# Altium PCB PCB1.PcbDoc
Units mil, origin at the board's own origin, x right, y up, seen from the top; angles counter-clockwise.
Board outline 6299.21 x 3937.01 mil, 4 copper layers (Top Layer, Top inner, Bottom inner, Bottom Layer), stack 60.556 mil thick; 113 components, 82 nets, 381 pads, 76 vias.
Unrouted connection lines stored in the file: 50.
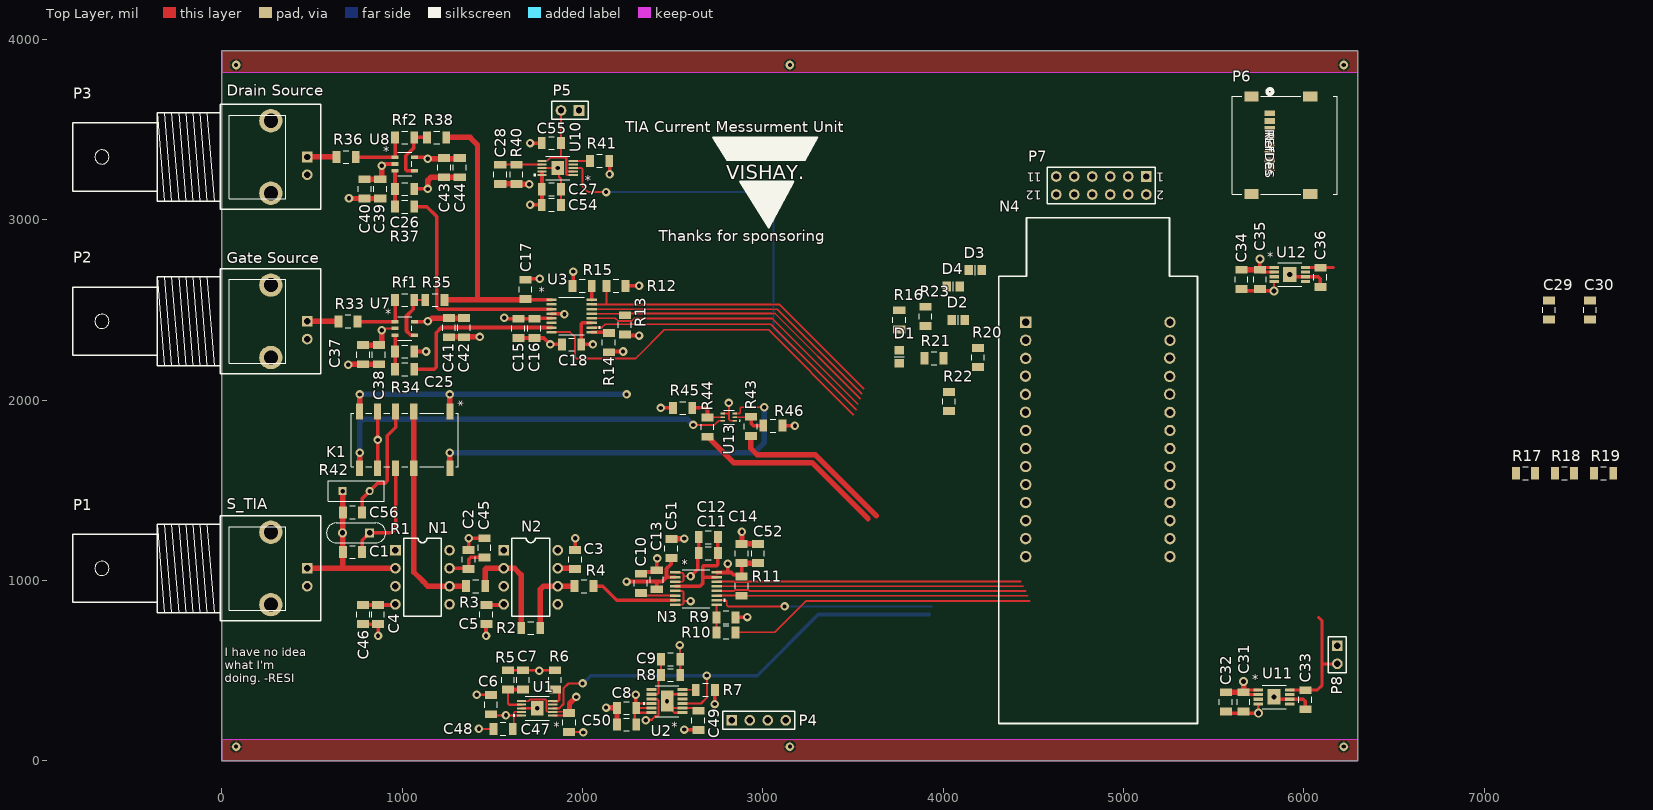
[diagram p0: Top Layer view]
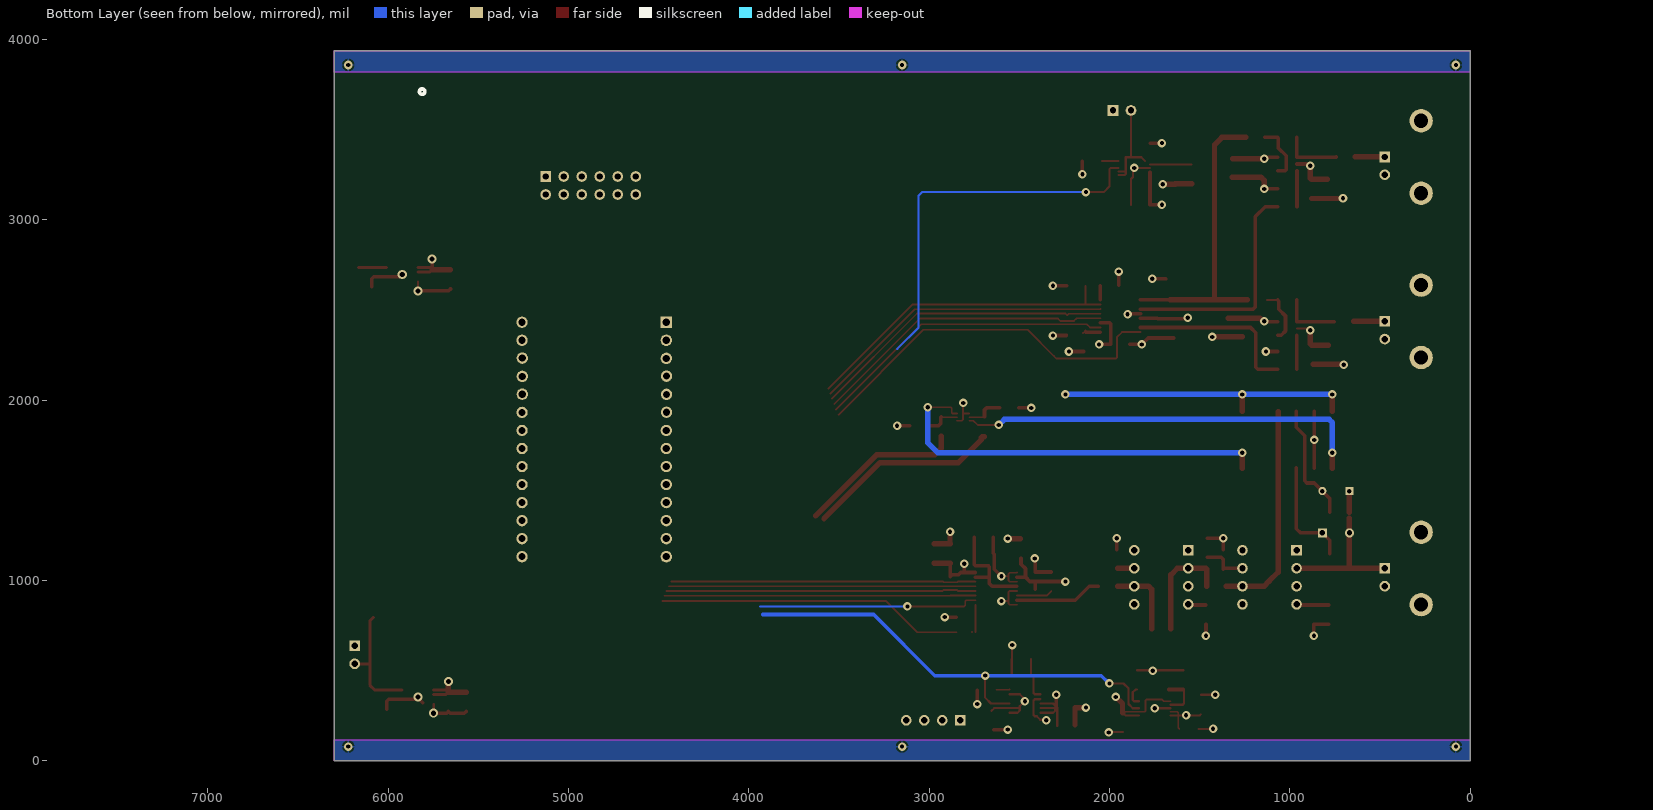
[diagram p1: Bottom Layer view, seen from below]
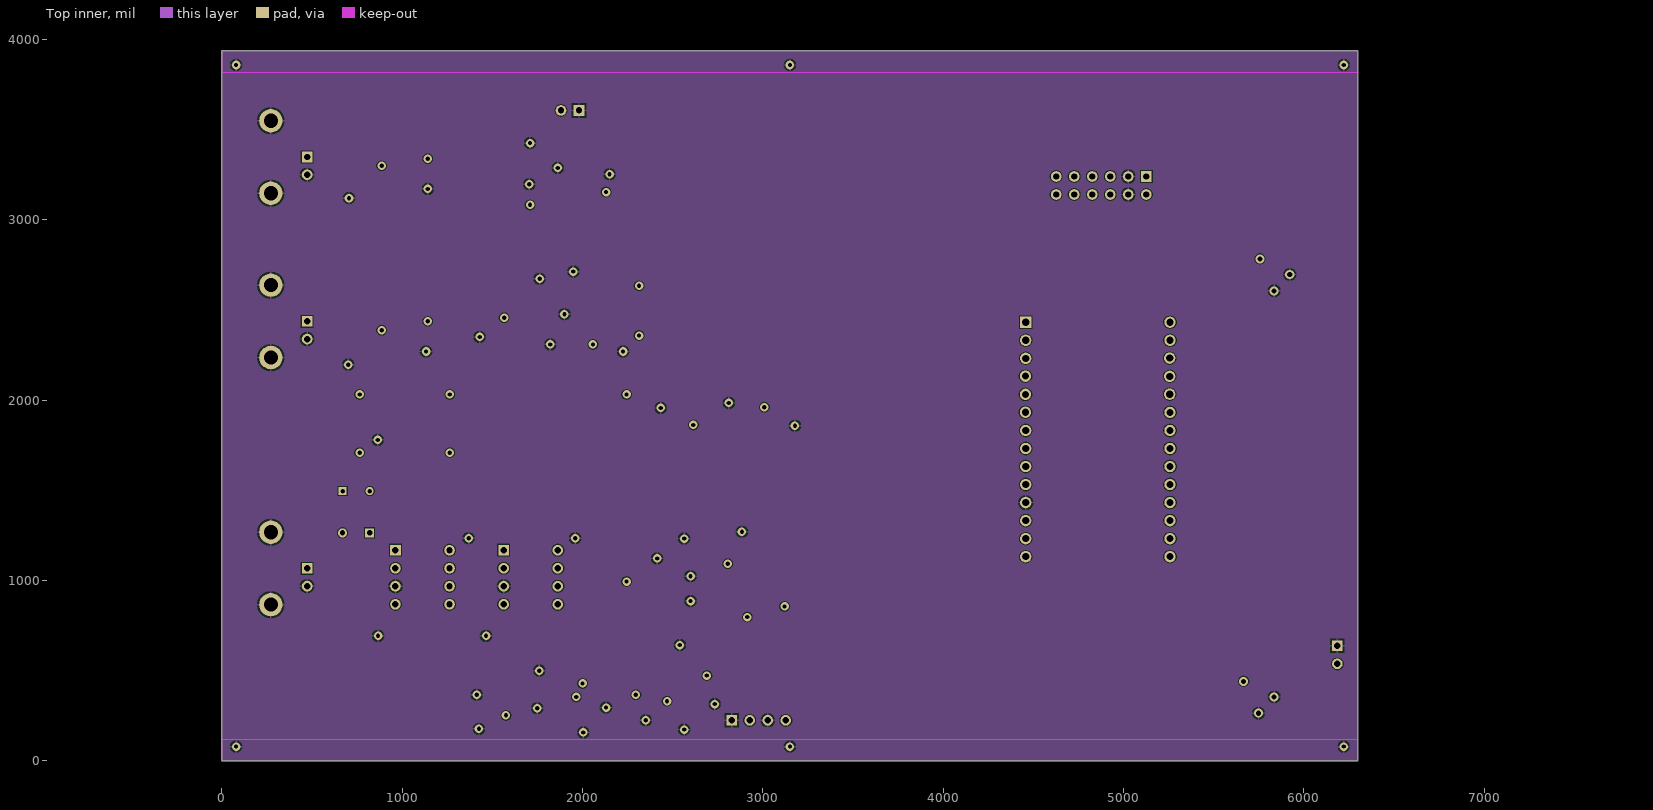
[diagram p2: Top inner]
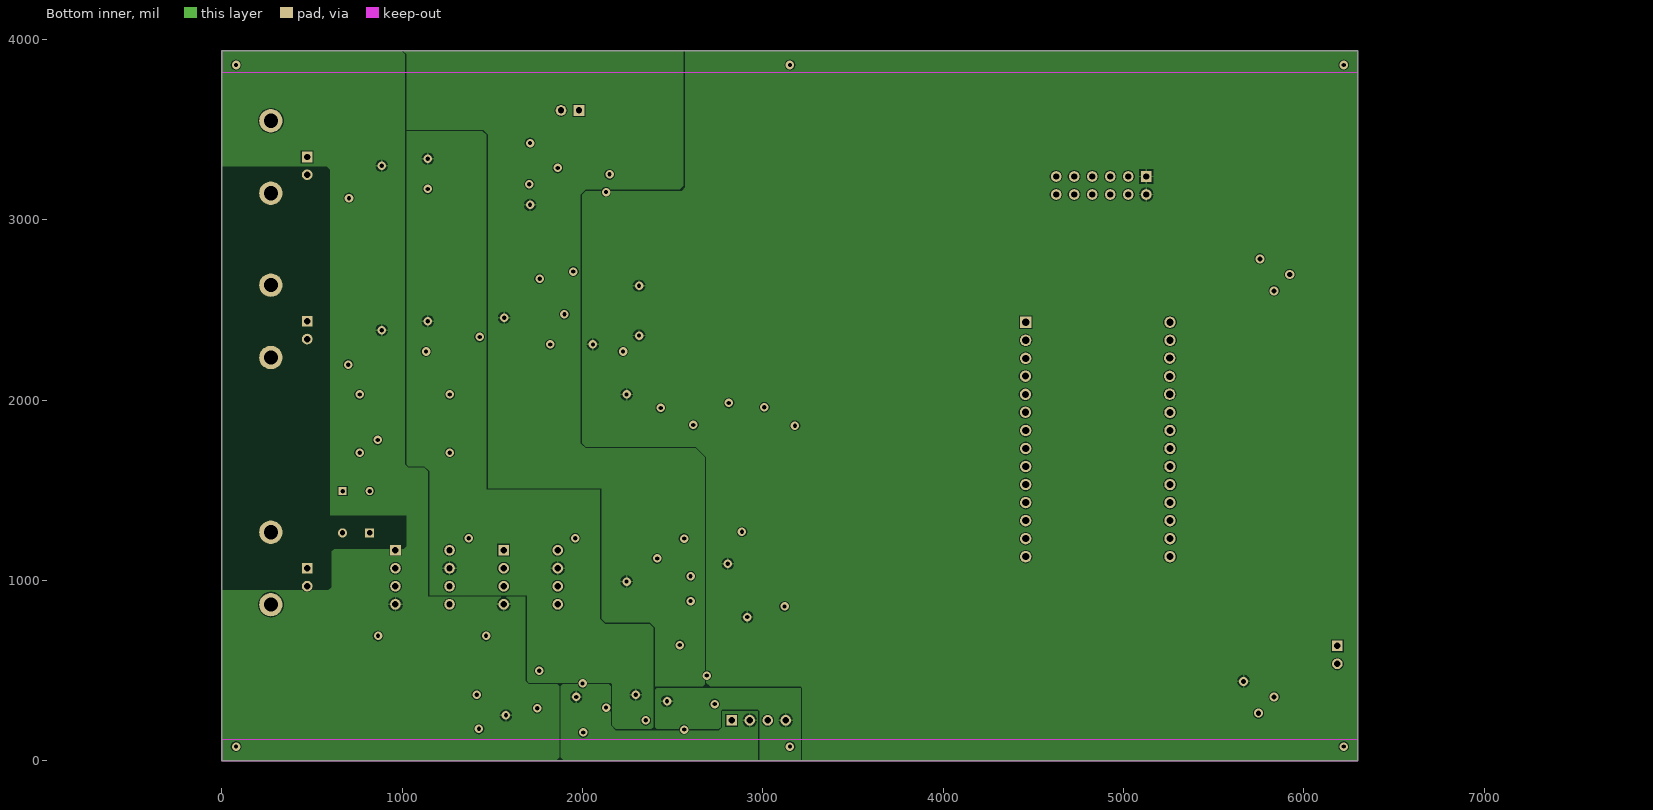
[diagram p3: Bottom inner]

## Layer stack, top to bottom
Top Solder: solder mask 0.4, Solder Resist, Dk 3.5
Top Layer: signal copper 1.4
Dielectric 4: prepreg 6, PP-006, Dk 4.4
Top inner: signal copper 1.378
Dielectric 1: dielectric 43, FR-4, Dk 4.8
Bottom inner: signal copper 1.378
Dielectric 5: prepreg 6, PP-006, Dk 4.4
Bottom Layer: signal copper 1.4
Bottom Solder: solder mask 0.4, Solder Resist, Dk 3.5

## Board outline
0,0 6299.21,0 6299.21,3937.01 0,3937.01

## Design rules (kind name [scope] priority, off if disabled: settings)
Clearance [All] p1: gap=5 ignorepadtopadclearanceinfootprint=TRUE except(1: THPad-THPad)
MinimumSolderMaskSliver THT_21-0248A_Q3-1_MXM [HasFootprint('21-0248A_Q3-1_MXM')] p1: minsoldermaskwidth=0
MinimumSolderMaskSliver [All] p2: minsoldermaskwidth=5
PolygonConnect [All] p1: connectstyle=Relief reliefconductorwidth=10 reliefentries=4 polygonreliefangle="90 Angle" airgapwidth=10
RoutingVias [All] p1: holewidth=23.62 width=47.24 viastyle="Through Hole" minholewidth=11.81 minwidth=23.62 maxholewidth=39.37 maxwidth=78.74
SilkToSolderMaskClearance SilkToSolderMaskClearance_1 [HasFootprint('BNC_RA CON')] p1: minsilkscreentomaskgap=0 clearancetoexposedcopper=TRUE
SilkToSolderMaskClearance [IsPad] p2: minsilkscreentomaskgap=5 clearancetoexposedcopper=TRUE
SolderMaskExpansion [All] p1: expansion=4 istentingtop=FALSE
Width Source [InNet('M_source')] p1: maxlimit=100 minlimit=10 preferedwidth=30
Width Width_1 [All] p2: maxlimit=30 minlimit=10 preferedwidth=30
28 further rules are at their usual default settings.

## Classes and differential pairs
component class U_Digital_Psu: C31 C32 C33 C34 C35 C36 U11 U12
component class U_Analog_PSU_5: C27 C28 C54 R40 R41 U10
component class U_Source_TIA: C1 C2 C3 C4 C5 C45 C46 C56 K1 N1 N2 R1 R2 R3 R4 R42
component class U_OPV_psu: C6 C7 C8 C9 C47 C48 C49 C50 R5 R6 R7 R8 U1 U2
component class U_DAC_Buffer_Filter: C25 C26 C37 C38 C39 C40 C41 C42 C43 C44 R33 R34 R35 R36 R37 R38 Rf1 Rf2 U7 U8
component class U_CortexM3_dev: C29 C30 D1 D2 D3 D4 N4 P6 P7 R16 R17 R18 R19 R20 R21 R22 R23
component class U_ADC_8681: C10 C11 C12 C13 C14 C51 C52 N3 R9 R10 R11
component class U_AD_5689_DAC: C15 C16 C17 C18 R12 R13 R14 R15 U3
component class Top_Sheet: C55 P1 P2 P3 P4 P5 P8 R43 R44 R45 R46 U13

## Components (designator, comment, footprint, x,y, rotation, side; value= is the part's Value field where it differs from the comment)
C1 "22pF" C1206-KUE 724.41,1157.48 r0 top
C2 "100nF" C1206-KUE 1368.11,1116.14 r270 top
C3 "100nF" C1206-KUE 1958.66,1116.14 r270 top
C4 "100nF" C1206-KUE 866.14,811.02 r90 top
C5 "100nF" C1206-KUE 1466.54,811.02 r90 top
C6 "10uF" C1206-KUE 1492.39,311.02 r270 top
C7 "4.7uF" C1206-KUE 1669.55,448.82 r270 top
C8 "10uF" C1206-KUE 2244.09,293.35 r0 top
C9 "4.7uF" C1206-KUE 2488.19,562.99 r180 top
C10 "10uF" C1206-KUE 2322.83,984.25 r270 top
C11 "100nF" C1206-KUE 2696.85,1151.57 r0 top
C12 "10uF" C1206-KUE 2696.85,1240.16 r0 top
C13 "0.1uF" C1206-KUE 2411.42,1003.94 r270 top
C14 "0.1uF" C1206-KUE 2881.89,1149.61 r270 top
C15 "10uF" C1206-KUE 1643.7,2397.64 r90 top
C16 "0.1uF" C1206-KUE 1732.28,2397.64 r90 top
C17 "0.1uF" C1206-KUE 1683.07,2614.17 r270 top
C18 "0.1uF" C1206-KUE 1938.98,2309.06 r0 top
C25 "1uF" C1206-KUE 1013.78,2269.69 r180 top
C26 "1uF" C1206-KUE 1013.78,3171.26 r180 top
C27 "10uF" C1206-KUE 1826.77,3169.29 r180 top
C28 "4.7uF" C1206-KUE 1543.31,3251.97 r90 top
C29 "100nF" C1206-KUE 7358.27,2500 r90 top
C30 "1uF" C1206-KUE 7586.61,2500 r90 top
C31 "100nF" C1206-KUE 5665.35,326.77 r90 top
C32 "10uF" C1206-KUE 5566.93,326.77 r90 top
C33 "10uF" C1206-KUE 6007.87,338.58 r90 top
C34 "100nF" C1206-KUE 5653.54,2669.29 r90 top
C35 "10uF" C1206-KUE 5755.91,2669.29 r90 top
C36 "4.7uF" C1206-KUE 6090.55,2681.1 r90 top
C37 "100nF" C1206-KUE 783.46,2251.97 r90 top
C38 "1uF" C1206-KUE 870.08,2251.97 r90 top
C39 "100nF" C1206-KUE 877.95,3171.26 r90 top
C40 "1uF" C1206-KUE 791.34,3171.26 r90 top
C41 "100nF" C1206-KUE 1259.84,2401.57 r90 top
C42 "1uF" C1206-KUE 1342.52,2401.57 r90 top
C43 "100nF" C1206-KUE 1232.28,3289.37 r90 top
C44 "1uF" C1206-KUE 1318.9,3289.37 r90 top
C45 "10uF" C1206-KUE 1456.69,1181.1 r270 top
C46 "10uF" C1206-KUE 783.46,811.02 r270 top
C47 "10uF" C1206-KUE 1925.46,212.6 r90 top
C48 "100nF" C1206-KUE 1559.32,177.17 r0 top
C49 "10uF" C1206-KUE 2641.73,224.41 r90 top
C50 "100nF" C1206-KUE 2244.09,200.79 r0 top
C51 "10uF" C1206-KUE 2492.13,1177.17 r270 top
C52 "10uF" C1206-KUE 2972.44,1149.61 r270 top
C54 "100nF" C1206-KUE 1826.77,3082.68 r180 top
C55 "100nF" C1206-KUE 1826.77,3425.2 r0 top
C56 "22pF" C1206-KUE 724.41,1377.95 r0 top
D1 "GREEN" 6-0805_N-KUE 3755.92,2240.13 r90 top
D2 "GREEN" 6-0805_N-KUE 4082.68,2444.88 r0 top
D3 "RED" 6-0805_N-KUE 4177.17,2720.47 r0 top
D4 "RED" 6-0805_N-KUE 4055.12,2629.92 r0 top
K1 "G6SK-2F-TR DC3" "RELAY_G6SK-2F DC3_OMR" 763.78,1622.05 r270 top
N1 "LMC6001AIN/NOPB" DIP8 1112.2,1017.72 r270 top
N2 "LMC6001AIN/NOPB" DIP8 1712.6,1017.72 r270 top
N3 "ADS8681IPW" PW16_TEX 2627.95,954.72 r0 top
N4 "STM32F103" DIP28 4307.09,3011.81 r0 top
P1 "BNC" "BNC_RA CON" 472.44,1066.93 r0 top
P2 "BNC" "BNC_RA CON" 472.44,2437.01 r0 top
P3 "BNC" "BNC_RA CON" 472.44,3348.43 r0 top
P4 "Header 4" HDR1X4 2826.77,224.41 r0 top
P5 "Header 2" HDR1X2 1980.32,3606.3 r180 top
P6 "472192001" CONN_47219-2001_MOL 5893.7,3413.39 r270 top
P7 "Header 6X2" HDR2X6 5125.98,3240.16 r180 top
P8 "Header 2" HDR1X2 6185.04,637.8 r270 top
R1 "CNS020-10MP" RES_CNS020_VIS 818.9,1263.78 r180 top
R2 "10k" C1206-KUE 1712.6,736.22 r180 top
R3 "33k" C1206-KUE 1407.48,968.5 r180 top
R4 "10" C1206-KUE 2007.87,968.5 r180 top
R5 "78.7k" C1206-KUE 1586.61,448.82 r90 top
R6 "0" C1206-KUE 1846.72,448.82 r90 top
R7 "0" C1206-KUE 2681.1,393.7 r0 top
R8 "78.7k" C1206-KUE 2488.19,476.38 r0 top
R9 "10k" C1206-KUE 2795.28,795.28 r180 top
R10 "1k" C1206-KUE 2795.28,712.6 r180 top
R11 "4.7k" C1206-KUE 2881.89,968.5 r270 top
R12 "4.7k" C1206-KUE 2185.04,2633.86 r180 top
R13 "4.7k" C1206-KUE 2234.25,2417.32 r90 top
R14 "10k" C1206-KUE 2145.67,2318.9 r270 top
R15 "10k" C1206-KUE 1998.03,2633.86 r180 top
R16 "3.9k" C1206-KUE 3755.92,2444.86 r90 top
R17 "4.7k" C1206-KUE 7228.32,1594.48 r0 top
R18 "4.7k" C1206-KUE 7444.86,1594.48 r0 top
R19 "4.7k" C1206-KUE 7661.39,1594.48 r0 top
R20 "3.9k" C1206-KUE 4192.89,2236.21 r90 top
R21 "2.7k" C1206-KUE 3948.82,2232.28 r0 top
R22 "2.7k" C1206-KUE 4031.5,1992.13 r90 top
R23 "4.7k" C1206-KUE 3901.57,2464.57 r90 top
R33 "100" C1206-KUE 698.82,2437.01 r180 top
R34 "10k" C1206-KUE 1013.78,2171.26 r180 top
R35 "10k" C1206-KUE 1181.1,2555.12 r180 top
R36 "100" C1206-KUE 688.98,3348.43 r180 top
R37 "10k" C1206-KUE 1013.78,3072.83 r180 top
R38 "10k" C1206-KUE 1190.94,3456.69 r180 top
R40 "49.9k" C1206-KUE 1633.86,3251.97 r270 top
R41 "0" C1206-KUE 2094.49,3326.77 r0 top
R42 "Y0062100K000T9L" RES_S102K_7P62X2P67_VIS 669.29,1496.06 r0 top
R43 "1k" C1206-KUE 2933.07,1854.33 r270 top
R44 "1k" C1206-KUE 2692.91,1850.39 r270 top
R45 "10k" C1206-KUE 2555.12,1956.69 r180 top
R46 "10k" C1206-KUE 3055.12,1858.27 r0 top
Rf1 "20k" C1206-KUE 1013.78,2555.12 r180 top
Rf2 "20k" C1206-KUE 1013.78,3456.69 r180 top
U1 "LT3042EMSE#TRPBF" 05-08-1664_ADI 1748.29,291.34 r180 top
U2 "LT3094EMSE#TRPBF" MSE_05-08-1666_ADI 2468.5,330.71 r180 top
U3 "AD5689RBRUZ" RU_16_ADI 1938.98,2466.54 r0 top
U7 "OPA197IDBVR" DBV5_TEX 1013.78,2397.64 r0 top
U8 "OPA197IDBVR" DBV5_TEX 1013.78,3309.06 r0 top
U10 "LT3042EMSE#TRPBF" 05-08-1664_ADI 1862.2,3287.4 r180 top
U11 "TLV76733DGNR" VSSOP8_DGN_TEX 5834.65,354.33 r0 top
U12 "TLV76733DGNR" VSSOP8_DGN_TEX 5921.26,2696.85 r0 top
U13 "DMC2400UV-7" SON_400UV-7_DIO 2811.02,1905.51 r180 top

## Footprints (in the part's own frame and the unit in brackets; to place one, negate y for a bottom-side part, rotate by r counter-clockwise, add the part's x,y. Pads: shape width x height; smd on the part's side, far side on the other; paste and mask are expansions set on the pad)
05-08-1664_ADI [mil]
  rect 52.28x11 smd paste+0 mask+0: 1(-87.14,39.37) 2(-87.14,19.69) 3(-87.14,0) 4(-87.14,-19.68) 5(-87.14,-39.37) 6(87.14,-39.37) 7(87.14,-19.68) 8(87.14,0) 9(87.14,19.69) 10(87.14,39.37)
  rect 70x78 smd paste+0 mask+0: 11(0,0)
  silkscreen extent -66,-66 133,66, body extent -99,-61 99,61, height 43
6-0805_N-KUE [mm] "Chip Resistor, Body 2.0x1.2mm, IPC Medium Density"
  rect 1.2x1.4 smd: 1(-0.9,0) 2(0.9,0)
  silkscreen extent 0,-0.69 0,0.69, body extent -1,-0.63 1,0.63, height 0.8
"BNC_RA CON" [mm] "Connector; BNC Elbow"
  rect 1.5x1.5 hole 0.9: 1(0,0)
  round 3.3 hole 2: 2(-5.1,-5.1) 2(-5.1,5.1)
  round 1.5 hole 0.9: 2(0,-2.5)
  silkscreen extent -33,-7.4 1.9,7.4
C1206-KUE [mm] "Chip Capacitor, Body 3.2x1.6mm, IPC High Density"
  rect 1.1x1.7 smd: 1(-1.35,0) 2(1.35,0)
  silkscreen extent -0.4,-0.9 0.4,0.9, body extent -1.6,-0.8 1.6,0.8, height 0.95
CONN_47219-2001_MOL [mil]
  rect 32x59 smd paste+0 mask+0: 1(126.18,-82.61) 2(82.87,-82.61) 3(39.57,-82.61) 4(-3.74,-82.61) 5(-47.05,-82.61) 6(-90.35,-82.61) 7(-133.66,-82.61) 8(-176.97,-82.61)
  rect 57x79 smd paste-39.5 mask-39.5: G1(270.67,-184.97) G2(270.67,141.8) G3(-270.67,141.8) G4(-270.67,-184.97)
  silkscreen extent -312,-291 273,291
DBV5_TEX [mil]
  rect 38.5x20 smd paste+0 mask+0: 1(-53.75,37.4) 2(-53.75,0) 3(-53.75,-37.4) 4(53.75,-37.4) 5(53.75,37.4)
  silkscreen extent -40,-65 39,65, body extent -59,-60 59,60, height 57
DIP8 [mm] "DIP; 8 Leads; Row Spacing 7.62 mm; Pitch 2.54 mm"
  rect 1.5x1.5 hole 0.9: 1(-3.81,-3.81)
  round 1.5 hole 0.9: 2(-1.27,-3.81) 3(1.27,-3.81) 4(3.81,-3.81) 5(3.81,3.81) 6(1.27,3.81) 7(-1.27,3.81) 8(-3.81,3.81)
  silkscreen extent -5.5,-2.65 5.5,2.65
DIP28 [mm]
  round 1.6 hole 1: 1(24.13,-47.752) 2(24.13,-45.212) 3(24.13,-42.672) 4(24.13,-40.132) 5(24.13,-37.592) 6(24.13,-35.052) 7(24.13,-32.512) 8(24.13,-29.972) 9(24.13,-27.432) 10(24.092,-24.868) 11(24.092,-22.349) 12(24.092,-19.788) 13(24.13,-17.272) 14(24.13,-14.732) 15(3.81,-47.752) 16(3.81,-45.212) 17(3.81,-42.672) 18(3.81,-40.132) 19(3.81,-37.592) 20(3.81,-35.052) 21(3.81,-32.512) 22(3.81,-29.972) 23(3.772,-27.408) 24(3.772,-24.889) 25(3.772,-22.328) 26(3.81,-19.812) 27(3.81,-17.272)
  rect 1.6x1.6 hole 1: 28(3.81,-14.732)
  silkscreen extent 0,-71.26 28,0
HDR1X2 [mm] "Connector; Header; 2 Position"
  rect 1.5x1.5 hole 0.9: 1(0,0)
  round 1.5 hole 0.9: 2(2.54,0)
  silkscreen extent -1.27,-1.27 3.81,1.27
HDR1X4 [mm] "Connector; Header; 4 Position"
  rect 1.5x1.5 hole 0.9: 1(0,0)
  round 1.5 hole 0.9: 2(2.54,0) 3(5.08,0) 4(7.62,0)
  silkscreen extent -1.27,-1.27 8.89,1.27
HDR2X6 [mm] "Connector; Header; 6x2 Position"
  rect 1.5x1.5 hole 0.9: 1(0,0)
  round 1.5 hole 0.9: 2(0,2.54) 3(2.54,0) 4(2.54,2.54) 5(5.08,0) 6(5.08,2.54) 7(7.62,0) 8(7.62,2.54) 9(10.16,0) 10(10.16,2.54) 11(12.7,0) 12(12.7,2.54)
  silkscreen extent -1.27,-1.27 13.97,3.81
MSE_05-08-1666_ADI [mil]
  rect 54.56x16.97 smd paste+0 mask+0: 1(-86,63.98) 2(-86,38.39) 3(-86,12.8) 4(-86,-12.8) 5(-86,-38.39) 6(-86,-63.98) 7(86,-63.98) 8(86,-38.39) 9(86,-12.8) 10(86,12.8) 11(86,38.39) 12(86,63.98)
  rect 69x116 smd paste-57.5 mask+0: 13(0,0)
  silkscreen extent -66,-87 133,87, body extent -99,-81 99,81, height 43
PW16_TEX [mil]
  rect 58x14 smd paste+0 mask+0: 1(-115,89.57) 2(-115,63.98) 3(-115,38.39) 4(-115,12.79) 5(-115,-12.8) 6(-115,-38.39) 7(-115,-63.98) 8(-115,-89.57) 9(115,-89.57) 10(115,-63.98) 11(115,-38.39) 12(115,-12.8) 13(115,12.79) 14(115,38.39) 15(115,63.98) 16(115,89.57)
  silkscreen extent -76,-105 164,106, body extent -130,-101 130,101, height 47
"RELAY_G6SK-2F DC3_OMR" [mil]
  rect 87x39 smd paste+0 mask+0: 1(-314.96,500) 3(-314.96,300) 4(-314.96,200) 5(-314.96,100) 6(-314.96,0) 7(0,0) 8(0,100) 9(0,200) 10(0,300) 12(0,500)
  silkscreen extent -306,-46 -9,546
RES_CNS020_VIS [mil]
  rect 50x50 hole 30 paste-25 mask+0: 1(0,0)
  round 50 hole 30 paste-25 mask+0: 2(150,0)
  silkscreen extent -89,-55 239,55, body extent -84,-50 234,50, height 260
RES_S102K_7P62X2P67_VIS [mil]
  rect 45x45 hole 25 paste-22.5 mask+0: 1(0,0)
  round 45 hole 25 paste-22.5 mask+0: 2(150,0)
  silkscreen extent -80,-58 230,58, body extent -75,-53 225,53, height 336
RU_16_ADI [mm]
  rect 1.461x0.351 smd paste+0 mask+0: 1(-2.825,2.275) 2(-2.825,1.625) 3(-2.825,0.975) 4(-2.825,0.325) 5(-2.825,-0.325) 6(-2.825,-0.975) 7(-2.825,-1.625) 8(-2.825,-2.275) 9(2.825,-2.275) 10(2.825,-1.625) 11(2.825,-0.975) 12(2.825,-0.325) 13(2.825,0.325) 14(2.825,0.975) 15(2.825,1.625) 16(2.825,2.275)
  silkscreen extent -1.81,-2.63 4.06,2.63, body extent -3.2,-2.5 3.2,2.5, height 1.2
SON_400UV-7_DIO [mil]
  rect 24x10 smd paste+0 mask+0: 1(-33.5,19.68) 2(-33.5,0) 3(-33.5,-19.69) 4(33.5,-19.69) 5(33.5,0) 6(33.5,19.68)
  silkscreen extent -62,-39 30,39, body extent -34,-34 34,34, height 24
VSSOP8_DGN_TEX [mil]
  rect 52.5x17 smd paste+0 mask+0: 1(-87.25,38.38) 2(-87.25,12.8) 3(-87.25,-12.8) 4(-87.25,-38.38) 5(87.25,-38.38) 6(87.25,-12.8) 7(87.25,12.8) 8(87.25,38.38)
  rect 73x85 smd paste+0 mask+0: EPAD(0,0)
  silkscreen extent -66,-66 66,66, body extent -99,-61 99,61, height 43

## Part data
C1 C2 C3 C4 C5 C6 C7 C8 C9 C10 C11 C12 C13 C14 C15 C16 C17 C18 C25 C26 C27 C28 C29 C30 C31 C32 C33 C34 C35 C36 C37 C38 C39 C40 C41 C42 C43 C44 C45 C46 C47 C48 C49 C50 C51 C52 C54 C55 C56: library part Capacitor, "Capacitor", Manufacturer=Kemet
D1 D2 D3 D4: library part LED0, "Typical INFRARED GaAs LED"
K1: "Description", Manufacturer_Name=Omron
N1 N2: library part LMC6001AINNOPB, "Ultra-Low Input Current Amplifier 8-PDIP -40 to 85", Manufacturer=NationalSemiconductor, Manufacturer_Name="Texas Instruments", PartNumber=LMC6001AIN
N3: "16-bit, 1MSPS 1-ch SAR ADC with programmable (Â±12V, Â±10V, Â±6V, Â±5V, Â±2.5V) input ranges on 5V supply 16-TSSOP -40 to 125", Manufacturer_Name="Texas Instruments"
P1 P2 P3: "BNC Elbow Connector"
P4: "Header, 4-Pin"
P5 P8: "Header, 2-Pin"
P6: "1.10mm Pitch microSD Card Connector, Hinge Type, Lead-Free", Manufacturer_Name="Molex Connector Corporation"
P7: "Header, 6-Pin, Dual row"
R1: library part CNS020-10KP, "CNS 020 10K 0,02% e2", Manufacturer_Name=Vishay
R2 R3 R4 R5 R6 R7 R8 R9 R10 R11 R12 R13 R14 R15 R16 R17 R18 R19 R20 R21 R22 R23 R33 R34 R35 R36 R37 R38 R40 R41 R43 R44 R45 R46 Rf1 Rf2: library part ResistorSMD, "Resistor SMD", Manufacturer=AVX
R42: "No Description Available", Manufacturer_Name=Vishay
U1 U10: library part LT3042EMSETRPBF, "20V, 200mA, Ultralow Noise, Ultrahigh PSRR RF Linear Regulator", Manufacturer_Name="Analog Devices Inc"
U2: library part LT3094EMSETRPBF, "âˆ’20V, 500mA, Ultralow Noise, Ultrahigh PSRR Negative Linear Regulator", Manufacturer_Name="Analog Devices Inc"
U3: "Dual, 16-Bit nanoDAC+ with 2 ppm/Â°C Reference, SPI Interface", Manufacturer_Name="Analog Devices Inc"
U7 U8: "Single, 36-V, precision, rail-to-rail input output, low offset voltage op amp 5-SOT-23 -40 to 125", Manufacturer_Name="Texas Instruments"
U11 U12: "Adjustable- and fixed-output, 1-A, 16-V, positive-voltage low-dropout (LDO) linear regulator 8-HVSSOP -40 to 125", Manufacturer_Name="Texas Instruments"
U13: "Description", Manufacturer_Name="Diodes Inc"

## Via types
v1: diameter 47.24, hole 23.62, Top Layer to Bottom Layer, 70 vias
v2: diameter 50, hole 28, Top Layer to Bottom Layer, 6 vias

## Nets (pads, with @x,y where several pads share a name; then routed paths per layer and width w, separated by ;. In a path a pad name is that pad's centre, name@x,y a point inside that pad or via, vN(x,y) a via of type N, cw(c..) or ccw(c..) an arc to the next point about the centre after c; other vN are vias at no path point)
AVDD: C13.2 C15.2 C16.2 C27.2 C51.2 C54.2 N3.2 U3.5 U10.9 U10.10 | length 947
  Top Layer w10: v1(1564.96,2456.69) v1@1570.87,2450.79 ; C16.2 C16.2@1735.24,2453.74
  Top Layer w20: v1@1570.87,2450.79 C15.2 C16.2 ; v1(1708.66,3082.68) C54.2 ; C16.2@1735.24,2453.74 U3.5 ; C54.2@1775.07,3084.12 U10.10 U10.9@1775.07,3263.78 ; v1(2244.1,994.1) 2411.42,994.1 ; C13.2 2411.42,994.1 ; C51.2@2490.16,1122.05 2490.16,1090.55 2465.55,1065.94 2465.55,1018.7 ; N3.2 2465.55,1018.7 ; 2411.42,994.1 2440.95,994.1 2465.55,1018.7
damper_out: N2.6 R2.1 R4.2 | length 415.6
  Top Layer w10: N2.6 N2.6@1863.39,968.5
  Top Layer w30: R2.1@1765.75,732.28 1765.75,950.93 1783.32,968.5 1861.81,968.5 N2.6 ; N2.6@1863.39,968.5 R4.2
DVDD: C14.2 C18.2 C31.2 C32.2 C52.2 K1.1 K1.6 N3.16 P7.1 P7.2 R9.1 R11.1 R12.1 R13.1 U3.11 U11.1 U11.2 | length 2779.4
  Top Layer w10: R13.1 R13.1@2240.16,2358.27 ; v1@2911.42,795.28 v1(2913.39,797.24)
  Top Layer w17: C31.2@5678.15,367.13 U11.2 ; C31.2@5678.15,392.72 U11.1
  Top Layer w20: U3.11 1997.98,2428.15 1992.13,2422.29 C18.2 v1(2057.09,2309.06) ; R12.1 v1(2312.99,2633.86) ; R13.1@2240.16,2358.27 v1(2312.99,2358.27) ; N3.16 2805.12,1044.29 ; v1(2805.12,1092.52) 2805.12,1044.29 ; R9.1 v1@2911.42,795.28 ; R11.1@2874.72,1028.83 2870.83,1032.71 2835.4,1032.71 2823.82,1044.29 2805.12,1044.29 ; R11.1 C14.2
  Top Layer w30: K1.6 v1(763.78,2031.5) ; K1.1 v1(1263.78,2031.5) ; C14.2 C52.2 ; C32.2 C31.2 v2(5665.35,440.94)
  Bottom Layer w30: v1(763.78,2031.5) v1(1263.78,2031.5) v1(2244.09,2031.5)
DVDD_SD: C29.2 C30.2 C34.2 C35.2 P6.4 R17.1 R18.1 R19.1 R23.2 U12.1 U12.2 | length 294
  Top Layer w17: C35.2@5768.7,2709.65 U12.2 ; C35.2@5768.7,2735.24 U12.1
  Top Layer w20: C35.2 v2(5755.91,2783.46)
  Top Layer w30: C34.2 C35.2
GND: C2.1 C3.1 C4.1 C5.1 C6.1 C7.1 C8.1 C9.1 C10.1 C11.1 C12.1 C13.1 C14.1 C15.1 C16.1 C17.1 C18.1 C25.1 C26.1 C27.1 C28.1 C29.1 C30.1 C31.1 C32.1 C33.1 C34.1 C35.1 C36.1 C37.1 C38.1 C39.1 C40.1 C41.1 C42.1 C43.1 C44.1 C45.1 C46.2 C47.1 C48.1 C49.1 C50.1 C51.1 C52.1 C54.1 C55.1 D1.2 D2.2 D3.2 D4.2 K1.5 K1.8 N1.3 N2.3 N3.1 N3.3 N3.5 N3.8 N4.18 P1.2 P2.2 P3.2 P4.1 P4.3 P5.1 P6.6 P7.3 P7.4 P8.1 R5.2 R6.2 R7.2 R8.2 R14.2 R15.2 R40.2 R41.2 R45.2 R46.2 U1.8 U1.11 U2.9 U3.4 U10.8 U10.11 U11.4 U11.6 U11.EPAD U12.4 U12.6 U12.EPAD U13.1 U13.4 | length 6353.3
  Top Layer w10: C17.1 C17.1@1688.98,2673.23 ; C18.1 C18.1@1889.76,2312.99 ; R15.2 R15.2@1948.82,2637.8 ; R14.2@2141.73,2269.69 R14.2 ; N3.1@2511.97,1045.28 2513.92,1043.32 2553.2,1043.32 2559.06,1037.47 2559.06,1023.62 ; N3.8 2553.2,865.16 2559.06,871.02 2559.06,885.83 ; N3.5 2553.2,941.93 2559.06,936.07 2559.06,885.83 ; N3.3 2553.2,993.11 2559.06,998.97 2559.06,1023.62 ; v1(2598.43,885.83) 2559.06,885.83 ; v1(2598.43,1023.62) 2559.06,1023.62 ; U13.4 2805.17,1925.2 ; v1(2811.02,1984.25) 2811.02,1893.7 2818.9,1885.83 U13.1
  Top Layer w12: v1(1413.39,366.14) 1490.42,366.14 C6.1 ; v1(1425.2,177.17) C48.1 ; R5.2@1590.81,501.97 1758.14,501.97 v1(1760.11,500) 1762.07,501.97 R6.2 ; U1.8 v1(1748.29,291.34) ; U10.8 v1(1862.2,3287.4) 1868.87,3280.74 1868.87,3237.43 1879.92,3226.38 C27.1 C54.1 ; C47.1 2001.97,159.45 v1(2003.94,157.48) ; v1(2350.39,224.41) 2354.07,228.08 2383.53,228.08 2402.7,247.25 2414.34,247.25 2420.78,253.69 2420.78,333.99 2413.75,341.02 2384.99,341.02 U2.9 ; v1(2539.37,641.73) 2539.37,564.96 C9.1 R8.2 ; C49.1@2639.76,173.23 C49.1 ; R7.2@2732.28,391.73 R7.2 ; U11.4@5746.76,315.31 5746.76,265.05 v2(5748.03,263.78) ; U12.4 5834.01,2606.94 v2(5834.65,2606.3)
  Top Layer w20: C46.2 C4.1 v1(866.14,692.91) ; K1.8 K1.5 ; C25.1 v1(1131.89,2269.69) ; C26.1 v1(1141.73,3171.26) ; C2.1 v1(1368.11,1234.25) C45.1 ; v1(1464.57,692.91) C5.1@1464.57,755.91 ; C15.1 C16.1 1785.43,2344.49 v1(1820.87,2309.06) C18.1 ; C17.1@1688.98,2673.23 v1(1761.81,2673.23) ; v1(1708.66,3425.2) C55.1 ; U3.4 v1@1876.97,2479.33 ; R15.2@1948.82,2637.8 v1(1948.82,2712.6) ; C3.1 v1(1958.66,1234.25) ; R14.2@2141.73,2269.69 v1(2224.41,2269.69) ; v1(2149.61,3251.97) R41.2@2149.61,3324.8 ; C10.1@2322.84,1047.24 C13.1@2411.42,1047.24 ; C13.1 2411.42,1120.08 v1(2413.39,1122.05) ; v1(2433.07,1956.69) R45.2 ; v1(2562.99,173.23) C49.1@2639.76,173.23 ; v1(2598.43,1023.62) 2637.8,1062.99 2637.8,1145.67 C11.1 C12.1 ; v1(2732.28,314.96) R7.2@2732.28,391.73 ; C14.1 C14.1@2881.89,1204.73 ; R46.2 v1(3177.17,1858.27) ; C32.1 5576.77,263.78 5655.51,263.78 C31.1 5675.2,263.78 v2(5748.03,263.78) ; C34.1 5663.39,2606.3 v2(5834.65,2606.3) ; U11.EPAD@5808.15,321.83 U11.EPAD@5834.65,348.33 ; U11.EPAD@5847.44,341.54 U11.6 5996.16,341.54 6007.87,329.82 C33.1 ; U12.EPAD@5934.05,2684.06 U12.6 6078.84,2684.06 6090.55,2672.34 C36.1
  Top Layer w30: v1(700.79,2196.85) 702.76,2198.82 C38.1@866.14,2198.82 ; v1@706.69,3118.11 C40.1 C39.1 ; C37.1@787.4,2198.82 C38.1 ; v1(1141.73,3171.26) 1141.73,3218.65 1159.31,3236.22 C43.1 C44.1 ; C41.1@1261.81,2350.39 v1(1429.13,2350.39) ; C28.1 R40.2 ; R40.2@1634.84,3197.83 v1@1703.74,3197.83 ; v1(2129.92,295.28) 2130.88,294.31 C8.1@2189.98,294.31 ; C50.1 C8.1 ; C51.1@2493.11,1231.3 2562.01,1231.3 v1(2562.99,1232.28) ; C14.1 C52.1 ; C14.1@2883.86,1204.73 v1(2883.86,1269.69)
  other v1: 78.74,78.74 3149.61,78.74 6220.47,78.74 863.78,1779.53 1899.61,2476.38 704.72,3120.08 1704.72,3196.85 78.74,3858.27 3149.61,3858.27 6220.47,3858.27
  other v2: 5834.65,354.33 5921.26,2696.85
M_source: C1.1 C56.1 N1.2 P1.1 R1.2 R42.1 | length 887.7
  Top Layer w10: N1.2@961.42,1066.93 N1.2
  Top Layer w30: P1.1 669.29,1066.93 ; C56.1@669.29,1346.46 669.29,1066.93 ; C56.1@669.29,1377.95 R42.1 ; N1.2@961.42,1066.93 669.29,1066.93
neg_out: C2.2 C3.2 C8.2 C41.2 C42.2 C43.2 C44.2 C45.2 C50.2 N1.7 N2.7 U2.10 U2.11 U2.12 U7.5 U8.5 | length 1310
  Top Layer w10: v1@1139.76,2435.04 v1(1141.73,2437.01) ; C2.2@1363.39,1067.72 C2.2 ; C3.2@1953.94,1067.72 C3.2 C3.2@1962.6,1066.93
  Top Layer w12: C50.2@2289.37,192.91 2289.37,291.34 C8.2@2291.34,293.31 ; C8.2 2301.2,289.39 2301.2,278.43 2312.9,266.73 U2.12 ; C8.2@2303.15,308.17 2312.9,317.91 U2.10 ; C8.2@2304.13,292.32 U2.11
  Top Layer w20: U7.5 v1@1139.76,2435.04 ; U8.5 v1@1125.74,3346.46 ; N1.7 C2.2@1363.39,1067.72 ; C2.2 1368.11,1116.14 1379.92,1127.95 C45.2 ; C8.2@2293.31,295.28 2294.29,296.26 2294.29,365.16 v1(2295.28,366.14)
  Top Layer w30: v1(1141.73,2437.01) 1147.15,2437.01 1164.86,2454.72 C41.2 C42.2 ; v1(1141.73,3338.58) C44.2@1314.96,3338.58 ; N2.7 C3.2@1953.94,1067.72
NetC1_2: C1.2 K1.9 R1.1 | length 626.9
  Top Layer w20: C1.2@777.56,1148.04 C1.2 777.56,1222.44 R1.1 940.94,1263.78 964.57,1287.4 K1.9@964.57,1625.98
NetC7_2: C7.2 R5.1 U1.7 | length 233.8
  Top Layer w12: R5.1 1586.61,318.05 1593.64,311.02 U1.7
  Top Layer w20: R5.1@1590.81,395.67 C7.2
NetC9_2: C9.2 R8.1 U2.8 | length 234.2
  Top Layer w12: U2.8 2414.23,369.09 2421.26,376.12 2421.26,462.6 R8.1 C9.2
NetC25_2: C25.2 R34.2 U7.3 | length 189.2
  Top Layer w10: U7.3 U7.3@960.63,2359.64
  Top Layer w20: R34.2 C25.2 U7.3@960.63,2359.64
NetC26_2: C26.2 R37.2 U8.3 | length 199.1
  Top Layer w10: R37.2@960.03,3073.43 R37.2
  Top Layer w20: R37.2@960.03,3073.43 U8.3
NetC28_2: C28.2 R40.1 U10.7 | length 229.8
  Top Layer w12: C28.2@1545.28,3307.09 U10.7
NetC33_2: C33.2 C36.2 P8.2 U11.8 U12.8 | length 811.5
  Top Layer w17: U11.8 C33.2@6006.89,392.72 ; C33.2 6072.83,391.73 6100.79,419.69 6100.79,537.8 ; U12.8 C36.2@6089.57,2735.24 ; 6080.59,795.28 6100.79,775.08 6100.79,537.8 ; C36.2@6090.55,2736.22 6163.27,2736.22 ; P8.2 6100.79,537.8
NetC47_2: C47.2 P4.2 U1.1 U1.2 U1.6 | length 533.9
  Top Layer w10: U1.6 1699.52,330.71 1709.15,340.34 1793.44,340.34 1799.29,334.48 1799.29,277.51 1804.65,272.15 1834.93,272.15 U1.2 1919.55,271.65 C47.2 1911.68,251.97 U1.1 U1.1@1834.93,252.47
  Top Layer w30: C47.2 1925.46,270.66 1927.2,272.4 1927.2,316.7 v1(1964.83,354.33)
NetC49_2: C49.2 P4.4 U2.1 U2.2 U2.5 U2.13 | length 396.7
  Top Layer w12: U2.1 2508.86,266.73 2497,278.59 U2.13@2497,292.32 ; U2.5 2497,369.09 2468.5,340.59 v1(2468.5,330.71) 2497,302.21 U2.13@2497,292.32 ; C49.2@2653.54,277.56 2638.78,292.32 U2.2 U2.13@2497,292.32
NetC55_2: C55.2 P5.2 U10.1 U10.2 U10.6 | length 546
  Top Layer w12: 1803.15,3326.77 1822.83,3346.46 1909.45,3346.46 1909.45,3255.06 1916.48,3248.03 U10.1 ; 1880.32,3348.82 P5.2 ; 1909.45,3267.72 U10.2
NetC56_2: C56.2 K1.4 R42.2 | length 661.3
  Top Layer w20: C56.2 777.56,1454.33 R42.2 863.78,1540.55 905.61,1540.55 917.32,1552.27 917.32,1803.15 964.57,1850.39 964.57,1936.22 K1.4
NetD1_1: D1.1 R16.2
NetD2_1: D2.1 R20.2
NetD3_1: D3.1 R21.2
NetD4_1: D4.1 R22.2
NetK1_7: K1.7 U13.6 | length 2297.9
  Top Layer w10: v1(2614.17,1862.2) 2730.27,1862.2 2753.89,1885.83 U13.6
  Top Layer w30: K1.7 v1(763.78,1708.66)
  Bottom Layer w30: v1(763.78,1708.66) 763.78,1876.13 781.35,1893.7 2582.68,1893.7 v1(2614.17,1862.2)
NetK1_12: K1.12 U13.3 | length 2234.4
  Top Layer w10: U13.3 2868.16,1925.2 2874.02,1931.05 2874.02,1954.77 2879.87,1960.63 v1(3007.87,1960.63)
  Top Layer w30: K1.12 v1@1263.78,1700.79
  Bottom Layer w30: v1(1263.78,1708.66) 2952.76,1708.66 3007.87,1763.78 v1(3007.87,1960.63)
NetN2_2: N2.2 R2.2 R3.1 | length 608.8
  Top Layer w30: R3.1 1460.63,1061.86 1466.49,1067.72 N2.2 1623.23,1067.72 1659.45,1031.5 R2.2@1659.45,732.28
NetN3_7: N3.7 R4.1 | length 484.1
  Top Layer w20: R4.1 2112.2,968.5 2189.96,890.75 N3.7
NetN3_9: N3.9 R9.2 R10.2 | length 152.9
  Top Layer w10: R10.2@2742.95,713.43 N3.9 ; R10.2@2761.81,714.52 R10.2@2762.64,715.35
NetN3_11: N3.11 N4.6 R11.2 | length 1726
  Top Layer w10: N3.11 2880.91,916.34 R11.2 4468.5,915.36
NetN3_14: N3.14 N4.14 | length 1690
  Top Layer w10: N3.14 2743.94,994.1 2840.19,994.1 2844.28,990 2919.5,990 2923.59,994.1 4429.13,994.1
NetN4_2: N4.2
NetN4_3: N4.3 U10.3 | length 2126.7
  Top Layer w12: U10.3 1992.13,3287.4 2000,3279.53 2000,3185.04 2031.5,3153.54 v1(2129.92,3153.54)
  Bottom Layer w12: v1(2129.92,3153.54) 3039.37,3153.54 3059.06,3133.86 3059.06,2401.57 3176.28,2284.35
NetN4_4: N4.4 U12.5
NetN4_5: N4.5 R13.2 U3.13 | length 1692.6
  Top Layer w10: U3.13 2225.39,2479.33 R13.2 2244.09,2480.32 3066.93,2480.32 3539.37,2007.87
NetN4_9: N4.9 R20.1
NetN4_10: N4.10 R21.1
NetN4_11: N4.11 R22.1
NetN4_13: N4.13 R10.1 | length 1701.7
  Top Layer w10: R10.1 3064.96,712.6 3238.19,885.83 4478.35,885.83
NetN4_17: N4.17 R16.1
NetN4_21: N4.21
NetN4_25: N4.25 R12.2 U3.15 | length 1805.9
  Top Layer w10: U3.15 2131.89,2530.51 ; R12.2 2131.89,2530.51 ; 3559.06,2062.99 3091.54,2530.51 2131.89,2530.51
NetN4_26: N4.26 U3.10 | length 1669
  Top Layer w10: U3.10 2106.92,2402.56 2125.61,2421.26 3043.31,2421.26 3515.75,1948.82
NetN4_27: N4.27 U1.3 U2.3 | length 2621.8
  Top Layer w12: U1.3 1870.34,291.34 1893.96,314.96 1893.96,401.57 1921.52,429.13 v1(2000,429.13) ; U2.3 2656.5,317.91 2688.98,350.39 v1(2688.98,472.44)
  Bottom Layer w20: v1@2001.47,429.13 2044.78,472.44 v1(2688.98,472.44) 2968.5,472.44 3307.09,811.02 3921.26,811.02
  Bottom Layer w30: v1(2000,429.13) v1@2001.47,429.13
NetP2_1: P2.1 R33.2 | length 173.2
  Top Layer w30: P2.1 R33.2
NetP3_1: P3.1 R36.2 | length 163.4
  Top Layer w30: P3.1 R36.2
NetP6_1: P6.1 P6.8 R23.1
NetP7_6: P7.6 R44.2 | length 1085
  Top Layer w30: R44.2 2704.72,1797.24 2711.38,1790.59 2711.38,1778.78 2836.61,1653.54 3271.65,1653.54 3582.68,1342.52
NetP7_8: P7.8 R43.2 | length 920.7
  Top Layer w30: R43.2 2933.07,1732.28 2968.5,1696.85 3291.34,1696.85 3629.92,1358.27
NetP7_12: P7.12 U11.5
NetR6_1: R6.1 U1.5 | length 110.2
  Top Layer w12: U1.5 1863.31,330.71 1870.34,337.74 1870.34,380.02 1854.69,395.67 R6.1
NetR7_1: R7.1 U2.6 | length 73.9
  Top Layer w10: U2.6 2555.49,393.7 R7.1
NetR14_1: R14.1 U3.9 | length 101.6
  Top Layer w10: R14.1@2130.91,2386.81 R14.1
  Top Layer w20: U3.9 R14.1@2130.91,2376.97
NetR15_1: R15.1 U3.16 | length 78.2
  Top Layer w10: R15.1@2050.2,2632.87 R15.1
  Top Layer w20: U3.16 R15.1@2050.2,2632.87
NetR25_2: 
NetR26_2: 
NetR28_2: 
NetR29_2: 
NetR31_2: 
NetR32_2: 
NetR33_1: R33.1 Rf1.2 U7.1 | length 329.2
  Top Layer w10: R33.1 R33.1@753.94,2435.04 ; U7.1 U7.1@960.63,2435.64
  Top Layer w20: R33.1@753.94,2435.04 U7.1 ; U7.1@960.63,2435.64 Rf1.2
NetR34_1: R34.1 U3.7 | length 968.5
  Top Layer w20: R34.1 1177.26,2171.26 1188.98,2182.97 1188.98,2374.02 1217.52,2402.56 U3.7
NetR35_2: R35.2 Rf1.1 U7.4 | length 304
  Top Layer w10: Rf1.1 R35.2
  Top Layer w20: Rf1.1 1060.8,2548.98 1060.8,2503.71 1023.62,2466.54 1023.62,2383.76 1047.15,2360.24 U7.4
NetR36_1: R36.1 Rf2.2 U8.1 | length 328
  Top Layer w10: U8.1@958.06,3348.42 U8.1@960.63,3350.99
  Top Layer w20: R36.1 744.1,3346.46 U8.1 ; U8.1@960.63,3350.99 Rf2.2
NetR37_1: R37.1 U3.3 | length 1289.6
  Top Layer w20: R37.1 1135.83,3072.83 1190.95,3017.72 1190.95,2516.64 1202.66,2504.92 U3.3
NetR38_2: R38.2 Rf2.1 U8.4 | length 319.8
  Top Layer w10: Rf2.1@1062.99,3452.76 Rf2.1
  Top Layer w20: Rf2.1@1062.99,3452.76 1062.99,3397.64 1019.73,3354.38 1019.73,3277.51 1025.59,3271.65 U8.4 ; Rf2.1 R38.2
NetR41_1: R41.1 U10.5 | length 92
  Top Layer w12: U10.5 R41.1
NetR43_1: R43.1 R46.1 U13.2 | length 195.2
  Top Layer w10: U13.2 2927.17,1905.51 R43.1@2929.13,1907.48
  Top Layer w20: R43.1 2935.61,1904.94 2935.61,1869.98 2947.32,1858.27 R46.1
NetR44_1: R44.1 R45.1 U13.5 | length 212.4
  Top Layer w10: R44.1@2692.91,1907.48 2694.88,1905.51 U13.5
  Top Layer w20: R45.1 2681.2,1956.69 2692.91,1944.98 R44.1@2692.91,1907.48
pos_out: C4.2 C5.2 C6.2 C37.2 C38.2 C39.2 C40.2 C46.1 C48.2 N1.4 N2.4 U1.9 U1.10 U7.2 U8.2 | length 1089.1
  Top Layer w10: C46.1 783.46,862.2 C46.1@785.43,864.17 ; v1(885.83,2387.8) 896.65,2387.8 906.49,2397.64 U7.2 ; v1(885.83,3299.21) 896.65,3299.21 v1@906.49,3309.05 ; N1.4@958.66,864.17 N1.4 ; C6.2 1498.29,251.97 1618.37,251.97 ; N2.4@1559.06,864.17 N2.4 ; C48.2 1618.37,183.07 1618.37,251.97 ; U1.10 1618.37,251.97 ; U1.9 1624.23,271.65 1618.37,265.8 1618.37,251.97
  Top Layer w20: C46.1 785.43,864.17 C4.2 N1.4@958.66,864.17 ; v1@906.49,3309.05 U8.2 ; C5.2 N2.4@1559.06,864.17
  Top Layer w30: C37.2@787.4,2305.12 C38.2 879.17,2305.12 885.83,2311.77 v1(885.83,2387.8) ; C40.2 C39.2 879.17,3224.41 885.83,3231.06 v1(885.83,3299.21)
  other v1: 1575.07,251.97
ref_buff_dac: C17.2 R35.1 R38.1 U3.1 | length 1642.1
  Top Layer w20: C17.2@1663.39,2556.1 U3.1
  Top Layer w30: R35.1@1235.24,2556.1 1417.32,2556.1 ; R38.1 1375.98,3456.69 1417.32,3415.35 1417.32,2556.1 ; C17.2@1663.39,2556.1 1417.32,2556.1
REFCAP: C10.2 N3.6 | length 200.3
  Top Layer w10: C10.2@2322.84,940.95 2347.44,916.34 N3.6
REFIO: C11.2 C12.2 N3.4 N3.15 | length 568.7
  Top Layer w20: N3.4 2650.59,967.52 2667.32,984.25 2667.32,1018.7 ; N3.15 2667.32,1018.7 ; C12.2 C11.2 2750,1088.54 2744.14,1082.68 2673.18,1082.68 2667.32,1076.82 2667.32,1018.7
SPI1_CS_SRAM1: N4.24
SPI1_CS_SRAM2: N4.23
SPI1_CS_SRAM3: N4.28
SPI1_MISO: N3.13 N4.8 U3.8 | length 3760.6
  Top Layer w10: U3.8 1930.12,2376.97 1958.66,2348.43 1958.66,2236.17 1964.52,2230.32 2293.31,2230.32 2307.45,2244.46 2452.76,2389.76 3031.5,2389.76 3501.97,1919.29 ; N3.13 4441.93,967.52
SPI1_MOSI: N3.10 N4.22 U3.14 | length 2913.2
  Top Layer w10: U3.14 2051.18,2503.94 3078.74,2503.94 3547.24,2035.43 ; N3.10 2793.49,890.75 2799.35,884.89 2799.35,862.16 2805.2,856.3 v1(3120.08,856.3)
  Bottom Layer w10: v1(3120.08,856.3) 3937.01,856.3
SPI1_SCK: N3.12 N4.7 U3.12 | length 3400.8
  Top Layer w10: U3.12 2181.72,2453.74 2196.64,2438.82 2271.86,2438.82 2285.8,2452.76 3051.18,2452.76 3525.59,1978.35 ; N3.12 2839.2,941.93 2844.28,947.01 2919.5,947.01 2924.58,941.93 4455.71,941.93
SPI1_SRAM_MISO: P6.3 P7.7 R18.2
SPI1_SRAM_MOSI: P6.7 P7.9 R17.2
SPI1_SRAM_SCK: P6.5 P7.5
SPI2_NSS: P6.2 P7.11 R19.2
TIA_out: K1.3 K1.10 N1.6 R3.2 | length 1214
  Top Layer w20: R3.2@1353.54,967.72 R3.2
  Top Layer w30: K1.3 K1.10 1063.78,1046.46 1114.17,996.06 1142.52,967.72 N1.6 R3.2@1353.54,967.72
pads on no net: N1.1 N1.5 N1.8 N2.1 N2.5 N2.8 N4.1 N4.12 N4.15 N4.16 N4.19 N4.20 P6.G1 P6.G2 P6.G3 P6.G4 P7.10 U1.4 U2.4 U2.7 U3.2 U3.6 U10.4 U11.3 U11.7 U12.3 U12.7

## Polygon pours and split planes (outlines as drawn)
GND on Top inner "GND_L02_P000" (solid, pour order 0): 0,3937.01 0,0 6299.21,0 6299.21,3937.01
DVDD on Bottom inner "DVDD_L03_P007" (solid, pour order 7): 5606.3,0 6299.21,0 6299.21,3937.01 2568.9,3937.01 2568.9,3179.13 2549.21,3159.45 2017.72,3159.45 1998.03,3139.76 1998.03,1761.81 2017.72,1742.13 2627.95,1742.13 2687.01,1683.07 2687.01,433.07 2706.69,413.39 3208.66,413.39 3218.5,403.54 3218.5,0 3901.57,0
AVDD on Bottom inner "AVDD_L03_P008" (solid, pour order 8): 1023.62,3500 1448.82,3500 1476.38,3472.44 1476.38,1511.81 2106.3,1511.81 2106.3,787.4 2125.98,767.72 2372.05,767.72 2401.57,738.19 2401.57,413.39 2667.32,413.39 2677.17,423.23 2677.17,1683.07 2627.95,1732.28 2017.72,1732.28 1988.19,1761.81 1988.19,3139.76 2017.72,3169.29 2539.37,3169.29 2559.06,3188.98 2559.06,3937.01 1003.94,3937.01 1023.62,3917.32
NetC49_2 on Bottom inner "NETC49_2_L03_P005" (solid, pour order 5): 2982.28,187.01 2982.28,0 3208.66,0 3208.66,403.54 2411.42,403.54 2401.57,393.7 2401.57,187.01 2411.42,177.17 2755.91,177.17 2765.75,187.01 2765.75,275.59 2775.59,285.43 2972.44,285.43 2982.28,275.59
NetC47_2 on Bottom inner "NETC47_2_L03_P004" (solid, pour order 4): 2775.59,275.59 2972.44,275.59 2972.44,0 1899.61,0 1879.92,19.68 1879.92,413.39 1889.76,423.23 2145.67,423.23 2155.51,413.39 2155.51,196.85 2185.04,167.32 2755.91,167.32 2775.59,187.01
neg_out on Bottom inner "NEG_OUT_L03_P003" (solid, pour order 3): 2372.05,757.87 2125.98,757.87 2096.46,787.4 2096.46,1503.94 1466.54,1503.94 1466.54,3470.47 1444.88,3492.13 1023.62,3492.13 1023.62,1643.7 1033.46,1633.86 1122.05,1633.86 1151.57,1604.33 1151.57,917.32 1692.91,917.32 1692.91,442.91 1702.76,433.07 2155.51,433.07 2165.35,423.23 2165.35,196.85 2185.04,177.17 2381.89,177.17 2391.73,187.01 2391.73,738.19
pos_out on Bottom inner "POS_OUT_L03_P002" (solid, pour order 2): 590.55,944.88 606.3,960.63 610.24,960.63 610.24,1161.42 622.05,1173.23 1007.87,1173.23 1023.62,1188.98 1023.62,1362.2 600.39,1362.2 600.39,3277.56 580.71,3297.24 0,3297.24 0,3937.01 994.09,3937.01 1013.78,3917.32 1013.78,1643.7 1033.46,1624.02 1122.05,1624.02 1141.73,1604.33 1141.73,909.45 1683.07,909.45 1683.07,442.91 1702.76,423.23 1860.24,423.23 1870.08,413.39 1870.08,19.68 1850.39,0 0,0 0,944.88
GND on Top Layer "GND_L01_P010" (solid, pour order 10): 6299.21,118.11 6299.21,0 0,0 0,118.11
GND on Top Layer "GND_L01_P009" (solid, pour order 9): 0,3937.01 0,3818.9 6299.21,3818.9 6299.21,3937.01
no net on Top Overlay "NONET_L-01_P-001" (solid, pour order 18): 2717.17,3460.63 3307.72,3460.63 3032.13,2948.82
no net on Top Solder (solid): 417.32,1031.5 437.01,1011.81 996.06,1011.81 1015.75,1031.5 1015.75,1102.36 996.06,1122.05 732.28,1122.05 712.6,1141.73 712.6,1519.69 692.91,1539.37 645.67,1539.37 625.98,1519.69 625.98,1141.73 606.3,1122.05 437.01,1122.05 417.32,1102.36
no net on Top Solder "NONET_L03_P-001" (solid): 6299.21,3937.01 6299.21,3818.9 0,3818.9 0,3937.01
no net on Top Solder "NONET_L03_P-001" (solid): 0,118.11 0,0 6299.21,0 6299.21,118.11
GND on Bottom Layer "GND_L04_P011" (solid, pour order 11): 6299.21,3937.01 6299.21,3818.9 0,3818.9 0,3937.01
GND on Bottom Layer "GND_L04_P006" (solid, pour order 6): 6299.21,118.11 6299.21,0 0,0 0,118.11
no net on Bottom Solder "NONET_L03_P-001" (solid): 0,3937.01 0,3818.9 6299.21,3818.9 6299.21,3937.01
no net on Bottom Solder "NONET_L03_P-001" (solid): 0,118.11 0,0 6299.21,0 6299.21,118.11

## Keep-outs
Keep-Out Layer:
  region: 0,118.11 0,0 6299.21,0 6299.21,118.11
  region: 0,3937.01 0,3818.9 6299.21,3818.9 6299.21,3937.01

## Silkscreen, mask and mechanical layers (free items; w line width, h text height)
Top Overlay:
  pour cut-out: 2795.28,3326.77 3248.03,3326.77 3248.03,3216.54 2795.28,3216.54
  text "Drain Source" at 27.68,3689.1 h60
  text "TIA Current Messurment Unit" at 2236.22,3484.25 h60
  text "VISHAY." at 2795.28,3224.41 h78.74
  text "Thanks for sponsoring" at 2421.39,2882.32 h60
  text "Gate Source" at 27.68,2759.97 h60
  text "S_TIA" at 27.68,1395.95 h60
  text "I have no idea / what I'm  / doing. -RESI" at 15.75,437.01 h47.24
Mechanical 1:
  the board outline again, w10

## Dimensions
0,0 to 0,1062.99 on Mechanical 1
0,0 to 0,3346.46 on Mechanical 1
0,3818.9 to 0,3937.01 on Mechanical 1
0,118.11 to 0,0 on Mechanical 1
0,0 to 0,3937.01 on Mechanical 1
0,0 to 6299.21,0 on Mechanical 1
